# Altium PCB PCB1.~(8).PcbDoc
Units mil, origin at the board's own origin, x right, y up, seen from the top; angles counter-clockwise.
Board outline 6000 x 4000 mil, 2 copper layers (Top Layer, Bottom Layer); 27 components, 29 nets, 115 pads, 22 vias.
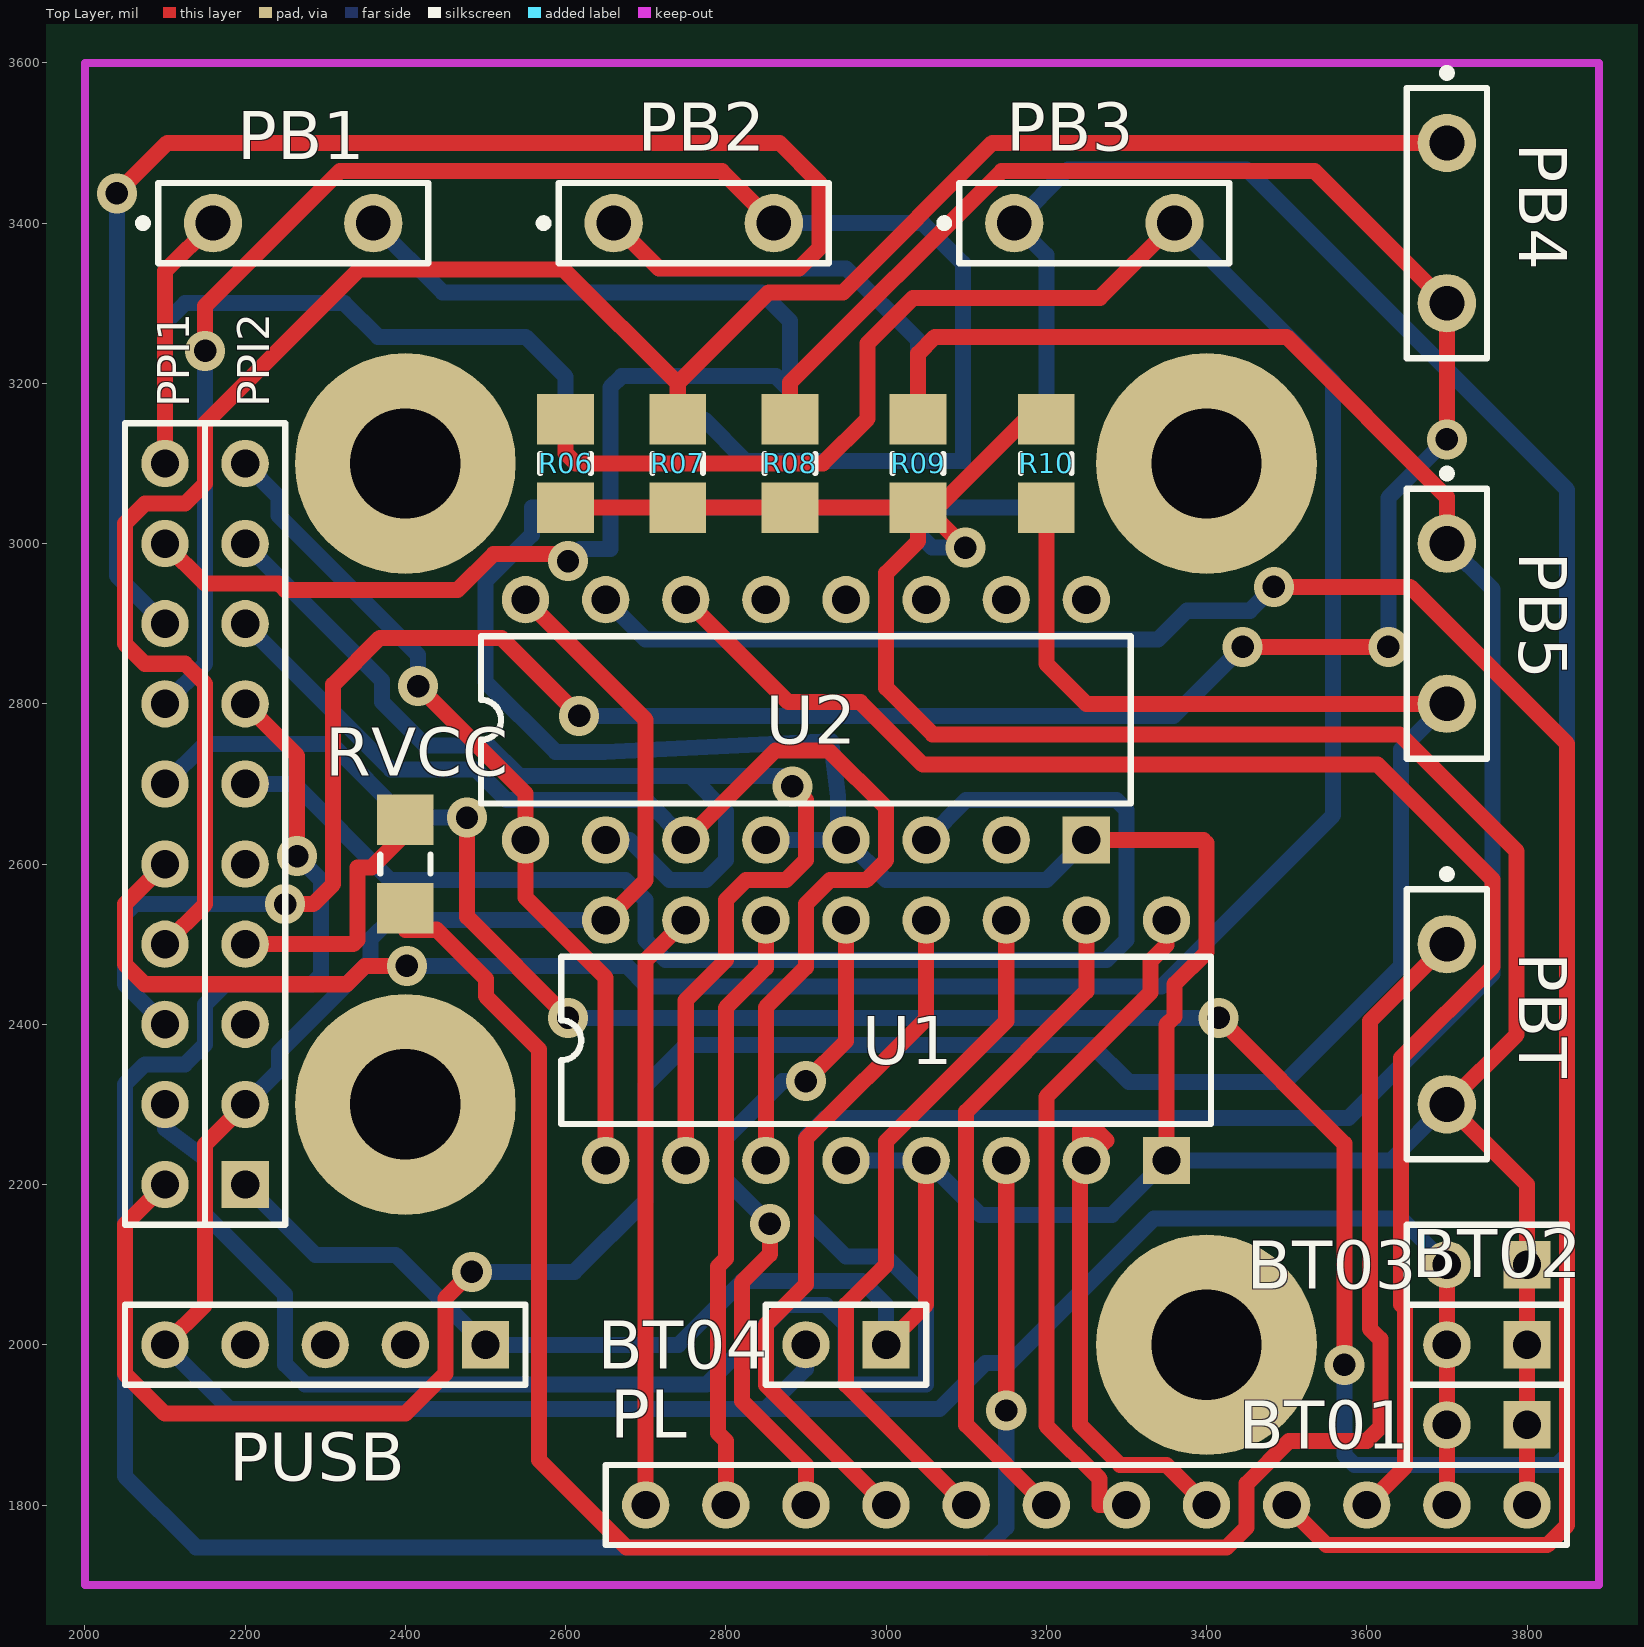
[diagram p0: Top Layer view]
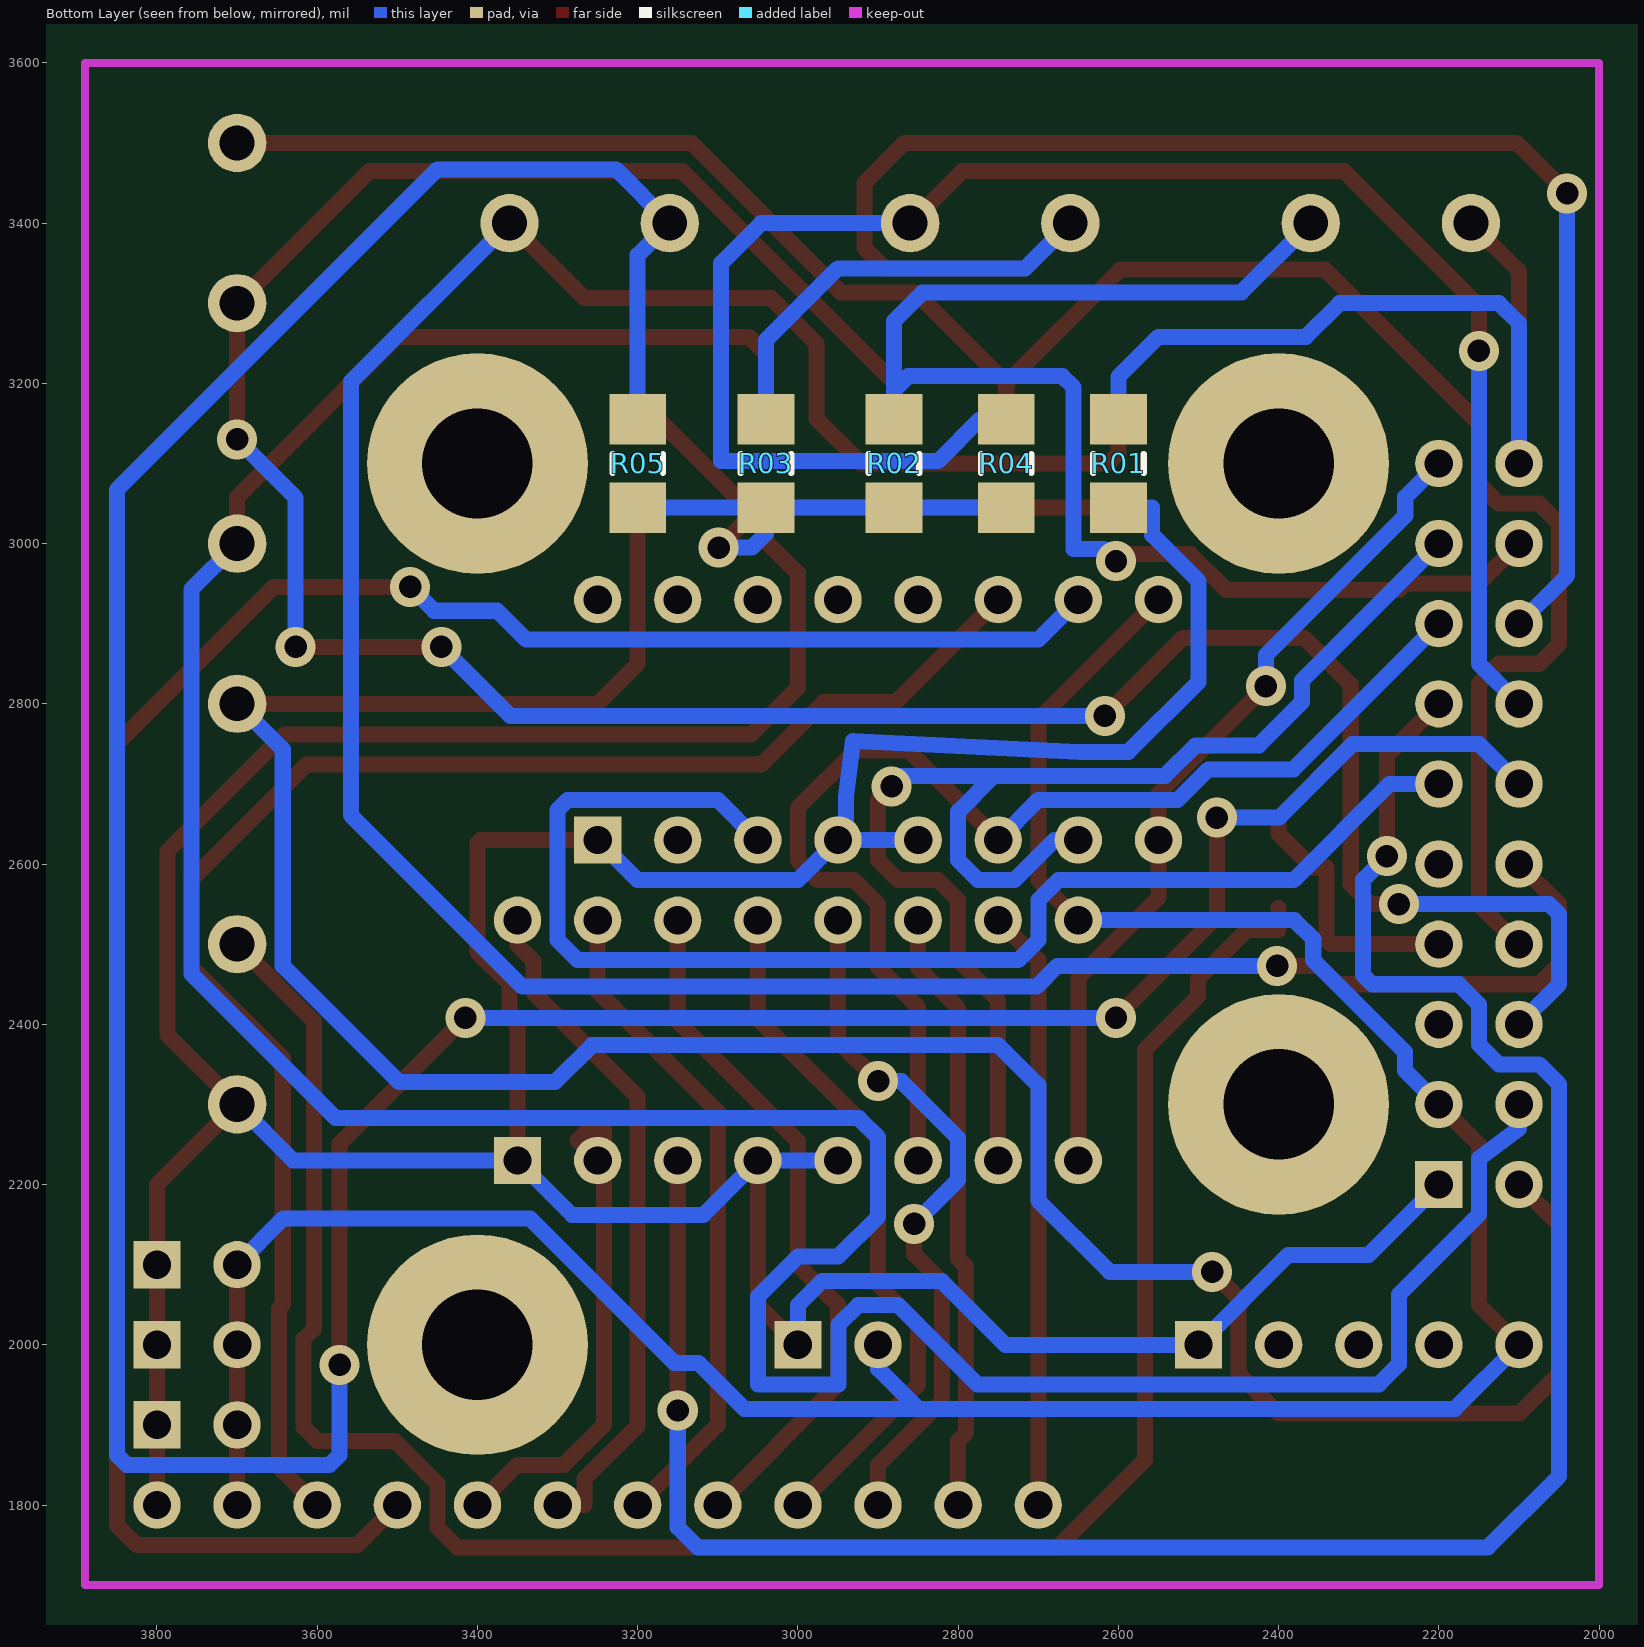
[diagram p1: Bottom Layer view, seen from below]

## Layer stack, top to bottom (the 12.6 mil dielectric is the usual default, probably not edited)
Top Layer: signal copper 1.4
Dielectric: dielectric 12.6, FR-4, Dk 4.8
Bottom Layer: signal copper 1.4

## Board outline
1000,1000 7000,1000 7000,5000 1000,5000

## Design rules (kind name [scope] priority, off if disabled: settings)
Clearance [All] p1: gap=10
ComponentClearance [All] p1: gap=10 collisioncheckmode=3 verticalgap=10
PolygonConnect [All] p1: connectstyle=Relief reliefconductorwidth=10 reliefentries=4 polygonreliefangle="90 Angle"
RoutingVias [All] p1: holewidth=28 width=50 viastyle="Through Hole" minholewidth=28 minwidth=50 maxholewidth=28 maxwidth=50
SolderMaskExpansion [All] p1: expansion=4
TestPointUsage [All] p1: valid=0 allowmultiple=FALSE
Testpoint [All] p1: side=15 testpointundercomponent=TRUE minsize=40 maxsize=100 preferedsize=60 minholesize=0 maxholesize=40 preferedholesize=32 testpointgrid=1 style=1023 order=0123456789
Width Width_2 [All] p1: maxlimit=30 minlimit=15 preferedwidth=20
Width Width_1 [InNet('VCC')] p2: maxlimit=30 minlimit=20 preferedwidth=30
Width [InNet('GND')] p3: maxlimit=30 minlimit=20 preferedwidth=30
18 further rules are at their usual default settings.

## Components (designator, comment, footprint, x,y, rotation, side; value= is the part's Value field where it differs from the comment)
BT01 "Header 2" HDR1X2 3800,1900 r180 top
BT02 "Header 2" HDR1X2 3800,2000 r180 top
BT03 "Header 2" HDR1X2 3800,2100 r180 top
BT04 "Header 2" HDR1X2 3000,2000 r180 top
PB1 "Header 2" SPST-2 2260,3400 r0 top
PB2 "Header 2" SPST-2 2760,3400 r0 top
PB3 "Header 2" SPST-2 3260,3400 r0 top
PB4 "Header 2" SPST-2 3700,3400 r270 top
PB5 "Header 2" SPST-2 3700,2900 r270 top
PBT "Header 2" SPST-2 3700,2400 r270 top
PL "Header 12" HDR1X12 2700,1800 r0 top
PPI1 "Header 10" HDR1X10#1 2100,3100 r270 top
PPI2 "Header 10" HDR1X10#2 2200,3100 r270 top
PUSB "Header 5" HDR1X5 2100,2000 r0 top
R01 "Res1" 3216[1206] 2600,3100 r90 bottom
R02 "Res1" 3216[1206] 2880,3100 r90 bottom
R03 "Res1" 3216[1206] 3040,3100 r90 bottom
R04 "Res1" 3216[1206] 2740,3100 r90 bottom
R05 "Res1" 3216[1206] 3200,3100 r90 bottom
R06 "Res1" 3216[1206] 2600,3100 r90 top
R07 "Res1" 3216[1206] 2740,3100 r90 top
R08 "Res1" 3216[1206] 2880,3100 r90 top
R09 "Res1" 3216[1206] 3040,3100 r90 top
R10 "Res1" 3216[1206] 3200,3100 r270 top
RVCC "Res1" 3216[1206] 2400,2600 r90 top
U1 "SN74HC138D" DIP-16 3000,2380 r0 top
U2 "SN74HC138D" DIP-16 2900,2780 r0 top

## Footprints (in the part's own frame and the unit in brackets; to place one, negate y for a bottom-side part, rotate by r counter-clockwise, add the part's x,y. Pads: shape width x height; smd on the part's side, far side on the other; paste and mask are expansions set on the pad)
3216[1206] [mm] "Chip Resistor; Body 3.2 x 1.6 mm (LxW typ)"
  rect 1.6x1.8 smd: 1(-1.4,0) 2(1.4,0)
  silkscreen extent -0.3,-0.8 0.3,0.8
DIP-16 [mm] "DIP; 16 Leads; Row Spacing 7.62 mm; Pitch 2.54 mm"
  round 1.5 hole 0.9: 1(-8.89,-3.81) 2(-6.35,-3.81) 3(-3.81,-3.81) 4(-1.27,-3.81) 5(1.27,-3.81) 6(3.81,-3.81) 7(6.35,-3.81) 9(8.89,3.81) 10(6.35,3.81) 11(3.81,3.81) 12(1.27,3.81) 13(-1.27,3.81) 14(-3.81,3.81) 15(-6.35,3.81) 16(-8.89,3.81)
  rect 1.5x1.5 hole 0.9: 8(8.89,-3.81)
  silkscreen extent -10.3,-2.65 10.3,2.65
HDR1X2 [mm] "Connector; Header; 2 Position"
  rect 1.5x1.5 hole 0.9: 1(0,0)
  round 1.5 hole 0.9: 2(2.54,0)
  silkscreen extent -1.27,-1.27 3.81,1.27
HDR1X5 [mm] "Connector; Header; 5 Position"
  round 1.5 hole 0.9: 1(0,0) 2(2.54,0) 3(5.08,0) 4(7.62,0)
  rect 1.5x1.5 hole 0.9: 5(10.16,0)
  silkscreen extent -1.27,-1.27 11.43,1.27
HDR1X10#1 [mm] "Connector; Header; 10 Position"
  round 1.5 hole 0.9: 1(0,0) 2(2.54,0) 3(5.08,0) 4(7.62,0) 5(10.16,0) 6(12.7,0) 7(15.24,0) 8(17.78,0) 9(20.32,0) 10(22.86,0)
  silkscreen extent -1.27,-1.27 24.13,1.27
HDR1X10#2 [mm] "Connector; Header; 10 Position"
  round 1.5 hole 0.9: 1(0,0) 2(2.54,0) 3(5.08,0) 4(7.62,0) 5(10.16,0) 6(12.7,0) 7(15.24,0) 8(17.78,0) 9(20.32,0)
  rect 1.5x1.5 hole 0.9: 10(22.86,0)
  silkscreen extent -1.27,-1.27 24.13,1.27
HDR1X12 [mm] "Connector; Header; 12 Position"
  round 1.5 hole 0.9: 1(0,0) 2(2.54,0) 3(5.08,0) 4(7.62,0) 5(10.16,0) 6(12.7,0) 7(15.24,0) 8(17.78,0) 9(20.32,0) 10(22.86,0) 11(25.4,0) 12(27.94,0)
  silkscreen extent -1.27,-1.27 29.21,1.27
SPST-2 [mm] "Circuit Breaker; 2 Leads"
  round 1.85 hole 1.1: 1(-2.54,0) 2(2.54,0)
  silkscreen extent -4.89,-1.27 4.28,1.27

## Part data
BT01 BT02 BT03 BT04 PB1 PB2 PB3 PB4 PB5 PBT: "Header, 2-Pin"
PL: "Header, 12-Pin"
PPI1 PPI2: "Header, 10-Pin"
PUSB: "Header, 5-Pin"
R01 R02 R03 R04 R05 R06 R07 R08 R09 R10 RVCC: "Resistor"
U1 U2: "3-Line to 8-Line Decoder / Demultiplexer"

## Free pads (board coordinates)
  round 275.59 hole 137.8: 0(3400,3100) 1(2400,3100) 3(3400,2000)
  round 275.59 hole 137.8 paste+0: 2(2400,2300)

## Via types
v1: diameter 50, hole 28, Top Layer to Bottom Layer, 22 vias

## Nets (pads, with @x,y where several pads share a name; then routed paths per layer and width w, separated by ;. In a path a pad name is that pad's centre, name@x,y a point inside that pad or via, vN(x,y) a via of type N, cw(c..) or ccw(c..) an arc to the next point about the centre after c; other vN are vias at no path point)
GND: BT01.1 BT02.1 BT03.1 BT04.1 PBT.2 PL.12 PPI2.10 PUSB.5 R01.1 R02.1 R03.1 R04.1 R05.1 R06.1 R07.1 R08.1 R09.1 R10.1 U1.4 U1.5 U1.8 U2.4 U2.5 U2.8 | length 7230.3
  Top Layer w20: R06.1 R07.1 R08.1 R09.1 ; BT04.1 3050,2050 U1.5 ; v1(3099,2995) R09.1@3049.12,3044.88 ; R10.1 3174.24,3155.12 3064,3044.88 R09.1@3049.12,3044.88 ; U2.8 3396,2630 3400,2626 3400,2490 3360,2450 3360,2409.43 3350,2399.43 U1.8 ; PL.12 BT01.1 BT02.1 BT03.1 3800,2200 PBT.2 3787,2387 3787,2616 3641,2762 3058,2762 3000,2820 3000,2963 3040,3003 R09.1 ; R09.1 R09.1@3049.12,3044.88
  Bottom Layer w20: PPI2.10 2287.8,2112.2 2387.8,2112.2 PUSB.5 2740.94,2000 2820.47,2079.53 2970,2079.53 3000,2049.53 BT04.1 ; R01.1 2558,3044.88 2558,3010.86 2500,2952.86 2500,2827.5 2587.5,2740 2648.45,2740 2931.45,2753.55 2940,2684.96 U2.5@2940,2630 ; R04.1 R02.1 R03.1 ; U2.4 U2.5@2940,2630 ; U1.4 U1.5 3118.02,2161.98 3281.98,2161.98 U1.8 3630,2230 PBT.2 ; v1(3099,2995) 3057.5,2995 3040,3012.5 R03.1 ; R05.1 R03.1 ; U2.8 3200,2580 3000,2580 U2.5 U2.5@2940,2630
NetPB1_1: PB1.1 PPI1.1 R01.2 | length 1101.2
  Top Layer w20: PPI1.1 2100,3340 PB1.1
  Bottom Layer w20: PPI1.1 2100,3275 2125,3300 2324,3300 2366,3258 2550,3258 2600,3208 R01.2
NetPB1_2: PB1.2 PPI1.2 R02.2 | length 1740.9
  Top Layer w20: PPI1.2 2150,2950 2242,2950 2249.8,2942.2 2465.36,2942.2 2510.16,2987 2594,2987 v1(2603,2978)
  Bottom Layer w20: PB1.2 2446.42,3313.58 2844.42,3313.58 2880,3278 2880,3191.5 ; v1(2603,2978) 2618,2993 2656,2993 2656,3195 2670,3209 2862.5,3209 2880,3191.5 ; R02.2 2880,3191.5
NetPB2_1: PB2.1 PPI1.3 R03.2 | length 2396.7
  Top Layer w20: v1(2040,3437) 2103,3500 2867,3500 2917,3450 2917,3369 2891.58,3343.58 2716.42,3343.58 PB2.1
  Bottom Layer w20: v1(2040,3437) 2040,2960 PPI1.3 ; PB2.1 2716.42,3343.58 2950,3343.58 3040,3253.58 R03.2
NetPB2_2: PB2.2 PPI1.4 R04.2 | length 2205.3
  Top Layer w20: v1(2150,3240.5) 2150,3296.68 2318.32,3465 2795,3465 PB2.2
  Bottom Layer w20: PPI1.4 2150,2850 v1(2150,3240.5) ; R04.2 2772.88,3155.12 2825,3103 3096,3103 3096,3350 3046,3400 PB2.2
NetPB3_1: PB3.1 PPI1.5 R05.2 | length 4798.3
  Top Layer w20: v1(2477,2658) 2477,2534 v1(2603,2408) ; v1(3415,2408) 3572,2251 v1(3572,1975)
  Bottom Layer w20: PPI1.5 2150,2750 2307.57,2750 2399.57,2658 v1(2477,2658) ; v1(2603,2408) v1(3415,2408) ; R05.2 3200,3360 PB3.1 3227,3467 3450,3467 3850,3067 3850,1862.5 3837.5,1850 3584.5,1850 3572,1862.5 v1(3572,1975)
NetPB3_2: PB3.2 PPI1.6 R06.2 | length 3581.2
  Top Layer w20: PPI1.6 2050,2550 2050,2475 2075,2450 2326.84,2450 2349.84,2473 v1(2402,2473) ; R06.2 2600,3112.5 2612.5,3100 2921,3100 2976.93,3155.93 2976.93,3250 3033.68,3306.75 3266.75,3306.75 PB3.2
  Bottom Layer w20: v1(2402,2473) 2676.19,2473 2702.19,2447 3344,2447 3558,2661 3558,3202 PB3.2
NetPB4_1: PB4.1 PPI1.7 R07.2 | length 2669.6
  Top Layer w20: PPI1.7 2150,2550 2150,2825 2125,2850 2075,2850 2050,2875 2050,3025 2075,3050 2125,3050 2150,3075 2150,3150 2342,3342 2598,3342 2740,3200 ; R07.2 2740,3200 ; PB4.1 3132.84,3500 2946.42,3313.58 2853.58,3313.58 2740,3200
NetPB4_2: PB4.2 PPI1.8 R08.2 | length 3602.4
  Top Layer w20: v1(2250,2550) 2285,2550 2310,2575 2310,2824 2368.2,2882.2 2519.8,2882.2 v1(2617,2785) ; R08.2 2880,3200.79 3144.21,3465 3535,3465 PB4.2 v1(3700,3130) ; v1(3445,2871) v1(3627,2871)
  Bottom Layer w20: PPI1.8 2050,2450 2050,2537.5 2062.5,2550 v1(2250,2550) ; v1(2617,2785) 3359,2785 v1(3445,2871) ; v1(3627,2871) 3627,3057 v1(3700,3130)
NetPB5_1: PB5.1 PPI1.9 R09.2 | length 4120.6
  Top Layer w20: R09.2 3040,3237 3061,3258 3500,3258 3700,3058 PB5.1
  Bottom Layer w20: PPI1.9 2100,2269.76 2150,2232.57 2150,2162.5 2250,2062.5 2250,1975.47 2275,1950.47 2775.94,1950.47 2875,2049.53 2925,2049.53 2949.53,2025 2949.53,1950.47 3050,1950.47 3050,2060 3000,2110 2950,2110 2900,2160 2900,2259 2924,2283 3577,2283 3757,2463 3757,2943 PB5.1
NetPB5_2: PB5.2 PPI1.10 R10.2 | length 3345.7
  Top Layer w20: PPI1.10 2050,2150 2050,1964 2100,1914 2400,1914 2450,1964 2450,2058 v1(2483,2091) ; R10.2 3200,2850 3250,2800 PB5.2
  Bottom Layer w20: v1(2483,2091) 2611,2091 2700,2180 2700,2324 2750,2374 3257,2374 3303,2328 3498,2328 3643,2473 3643,2743 PB5.2
NetPBT_1: PBT.1 RVCC.1 | length 2618.5
  Top Layer w20: RVCC.1 2400,2518 2439,2518 2500.38,2456.62 2500.38,2435.07 2567,2368.45 2567,1856 2676,1747 3425,1747 3450,1772 3450,1826.84 3503.16,1880 3600,1880 3617,1897 3617,2007 3604,2020 3604,2404 PBT.1
NetPL_1: PL.1 U1.15 | length 750.7
  Top Layer w20: PL.1 2700,2480 U1.15
NetPL_2: PL.2 U1.14 | length 759
  Top Layer w20: PL.2 2800,1880 2790,1890 2790,2097.67 2800,2107.67 2800,2420.47 2850,2470.47 U1.14
NetPL_3: PL.3 U1.13 | length 879.5
  Top Layer w20: v1(2855,2151) 2855,2113 2820,2078 2820,1930 2900,1850 PL.3 ; v1(2900,2329) 2950,2379 U1.13
  Bottom Layer w20: v1(2855,2151) 2800,2206 2800,2258 2871,2329 v1(2900,2329)
NetPL_4: PL.4 U1.12 | length 875
  Top Layer w20: PL.4 2850,1950 2850,2025 2900,2075 2900,2257 3050,2407 U1.12
NetPL_5: PL.5 U1.11 | length 875
  Top Layer w20: PL.5 2950,1950 2950,2050 3000,2100 3000,2254 3150,2404 U1.11
NetPL_6: PL.6 U1.10 | length 833.6
  Top Layer w20: PL.6 3100,1900 3100,2291 3250,2441 U1.10
NetPL_7: PL.7 U1.9 | length 853.2
  Top Layer w20: PL.7 3266.5,1800 3266.5,1832.5 3200,1899 3200,2309.43 3330,2439.43 3330,2478.87 3350,2498.87 U1.9
NetPL_8: PL.8 U1.7 | length 642.6
  Top Layer w20: U1.7 3275,2255 3261,2269 3250,2269 3242,2269 3242,2230 3242,1900 3292,1850 3350,1850 PL.8
NetPL_9: PL.9 U2.15 | length 2685.3
  Top Layer w20: v1(3484,2946) 3654,2946 3850,2750 3850,1775 3825,1750 3550,1750 PL.9
  Bottom Layer w20: U2.15 2700,2880 3339.28,2880 3375.44,2916.17 3454.17,2916.17 v1(3484,2946)
NetPL_10: PL.10 U2.14 | length 2001.3
  Top Layer w20: U2.14 2878,2802 2967.98,2802 3045.98,2724 3613.58,2724 3757,2580.58 3757,2472 3643,2358 3643,2050 3647.8,2045.2 3647.8,1847.8 PL.10
NetPPI2_1: PPI2.1 U1.1 U2.1 | length 1056.4
  Top Layer w20: v1(2416,2822) 2550,2688 U2.1 2550,2558 2650,2458 U1.1
  Bottom Layer w20: PPI2.1 2242,3058 2242,3034.84 2416,2860.84 v1(2416,2822)
NetPPI2_2: PPI2.2 U1.2 U2.2 | length 1694.3
  Top Layer w20: U1.2 2750,2430 2800,2480 2800,2555 2825,2580 2875,2580 2900,2605 2900,2680 v1(2883,2697)
  Bottom Layer w20: PPI2.2 2371,2829 2371,2802 2424.75,2748.25 2503.75,2748.25 2542,2710 2755.53,2710 ; U2.2 2679.96,2630 2729.96,2580 2775,2580 2800,2605 2800,2665.53 2755.53,2710 ; v1(2883,2697) 2870,2710 2755.53,2710
NetPPI2_3: PPI2.3 U1.3 U2.3 | length 1516.6
  Top Layer w20: U2.3 2862,2742 2928,2742 3000,2670 3000,2605 2975,2580 2929.96,2580 2900,2550.04 2900,2471 2850,2421 U1.3
  Bottom Layer w20: PPI2.3 2381.75,2718.25 2487.82,2718.25 2526.07,2680 2700,2680 U2.3
NetPPI2_4: PPI2.4 U1.6 | length 2802.6
  Top Layer w20: PPI2.4 2265,2735 v1(2265,2610) ; v1(3150,1918) U1.6
  Bottom Layer w20: v1(2265,2610) 2295,2580 2295,2462 2283,2450 2175,2450 2150,2425 2150,2375 2125,2350 2075,2350 2050,2325 2050,1836 2139,1747 3125,1747 3150,1772 v1(3150,1918)
NetPPI2_5: PPI2.5 U2.6 | length 1669.2
  Bottom Layer w20: PPI2.5 2261.43,2700 2381.43,2580 2675,2580 2700,2555 2700,2505 2725,2480 3275,2480 3300,2505 3300,2667.5 3287.5,2680 3100,2680 U2.6
NetPPI2_7: PPI2.7 RVCC.2 | length 327.6
  Top Layer w20: PPI2.7 2335,2500 2340,2505 2340,2596 2358,2596 2400,2638 RVCC.2
VCC: BT01.2 BT02.2 BT03.2 BT04.2 PL.11 PPI2.9 PUSB.1 U1.16 U2.16 | length 3555
  Top Layer w20: PUSB.1 2150,2050 2150,2250 PPI2.9 ; U2.16 2700,2780 2700,2580 U1.16 ; PL.11 BT01.2 BT02.2 BT03.2
  Bottom Layer w20: PUSB.1 2180,1920 2850,1920 ; PPI2.9 2242.2,2342.2 2242.2,2365.36 2356.81,2479.97 2356.81,2506.57 2380.24,2530 U1.16 ; BT04.2 2900,1970 2850,1920 ; BT03.2 3642.2,2157.8 3334.64,2157.8 3154.14,1977.3 3124.14,1977.3 3066.84,1920 2850,1920
pads on no net: PPI2.6 PPI2.8 PUSB.2 PUSB.3 PUSB.4 U2.7 U2.9 U2.10 U2.11 U2.12 U2.13

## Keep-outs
Keep-Out Layer:
  lines w10: 2000,1700 2000,3600 3890,3600 3890,1700 2000,1700

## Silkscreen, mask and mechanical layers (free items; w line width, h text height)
Mechanical 1:
  lines w10: 2000,1700 2000,3600 3890,3600 3890,1710 2010,1710 2000,1700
